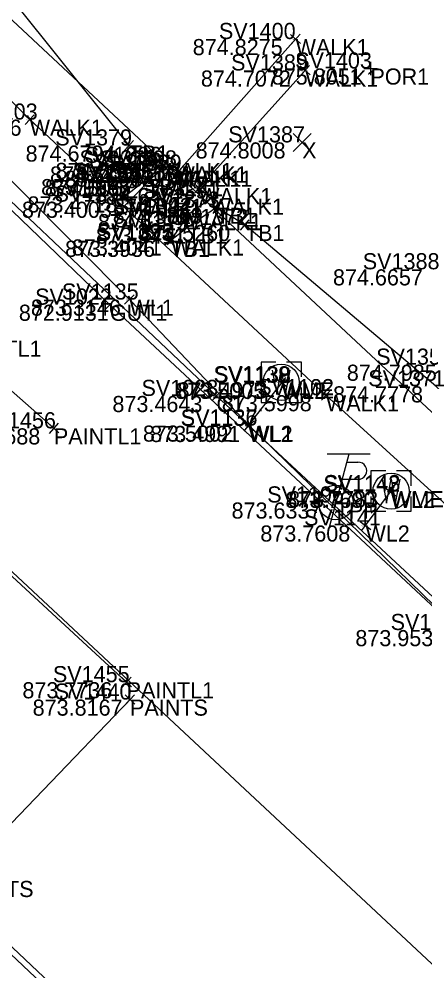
# Model space of a CAD drawing. Extents: x 1469677 to 1493262, y 375219 to 389293.
# Drawn here: x 1480132 to 1480162.2, y 379434.1 to 379505 of the extents above; entities that cross this region are included whole.
import ezdxf

# ---------------------------------------------------------------- set-up
doc = ezdxf.new("R2010")
doc.units = 0
for name, color, linetype in [('Building', 7, 'Continuous'), ('DR_X_Drive_Pipe', 7, 'Continuous'), ('DV_X_Lot_Line', 7, 'Continuous'), ('DV_X_Text', 7, 'Continuous'), ('GK_Visualization', 7, 'Continuous'), ('PNTELEV', 7, 'Continuous'), ('PNTNO', 7, 'Continuous'), ('PNTS', 7, 'Continuous'), ('PV_X_Curb', 7, 'Continuous'), ('RD_P_Text', 7, 'Continuous'), ('RW_P_Esmt_SW', 7, 'Continuous'), ('RW_P_Esmt_U', 7, 'Continuous'), ('SV_X_Mon_Cells_Found', 7, 'Continuous'), ('SV_X_Text', 7, 'Continuous'), ('SV_X_Text_Elevation', 7, 'Continuous')]:
    doc.layers.add(name, color=color, linetype=linetype)

msp = doc.modelspace()

# ---------------------------------------------------------------- linework, layer by layer
at = {"layer": 'Building'}
for points in [[(1480030.312, 379558.368), (1480048.994, 379540.544), (1480068.184, 379522.458), (1480086.697, 379505.162), (1480104.247, 379488.61), (1480122.276, 379471.896), (1480139.96, 379455.601)], [(1480134.548, 379474.499), (1480127.117, 379481.028)]]:
    msp.add_lwpolyline(points, dxfattribs=at)
at = {"layer": 'DR_X_Drive_Pipe'}
for points in [[(1480049.152, 379568.017), (1480068.611, 379550.193), (1480086.403, 379533.424), (1480090.024, 379530.079), (1480102.295, 379519.134), (1480111.734, 379511.473), (1480120.332, 379509.136), (1480127.535, 379501.668), (1480127.911, 379496.395), (1480140.166, 379484.084), (1480149.088, 379474.708), (1480164.726, 379459.482), (1480172.622, 379452.503), (1480197.813, 379429.111)], [(1480149.013, 379474.68), (1480151.509, 379477.889)], [(1480157.731, 379467.268), (1480159.603, 379469.773)]]:
    msp.add_lwpolyline(points, dxfattribs=at)
at = {"layer": 'DV_X_Lot_Line'}
for points in [[(1480215.341, 379421.047), (1480197.466, 379437.463), (1480177.803, 379455.97), (1480154.79, 379476.967), (1480132.747, 379497.48), (1480113.376, 379516.728), (1480110.754, 379519.04), (1480109.877, 379518.336), (1480091.944, 379535.267), (1480093.027, 379536.619), (1480090.219, 379539.243), (1480090.463, 379539.725), (1480084.681, 379544.882), (1480083.843, 379544.144), (1480066.818, 379560.524), (1480045.662, 379580.046)], [(1480140.103, 379491.371), (1480141.696, 379492.981), (1480142.433, 379494.261), (1480143.057, 379493.677), (1480143.514, 379493.991), (1480143.87, 379493.684), (1480152.532, 379503.479)], [(1480153.241, 379501.138), (1480145.352, 379492.379), (1480146.223, 379491.6), (1480144.597, 379490.448), (1480143.265, 379488.564)]]:
    msp.add_lwpolyline(points, dxfattribs=at)
at = {"layer": 'PNTELEV'}
for p, q in [((1480152.158, 379503.81), (1480152.907, 379503.148)), ((1480152.201, 379503.104), (1480152.864, 379503.853)), ((1480152.532, 379503.479), (1480152.532, 379503.479)), ((1480158.103, 379501.787), (1480158.103, 379500.787)), ((1480153.613, 379500.803), (1480152.87, 379501.473)), ((1480153.576, 379501.509), (1480152.907, 379500.766)), ((1480153.241, 379501.138), (1480153.241, 379501.138)), ((1480157.603, 379501.287), (1480158.603, 379501.287)), ((1480158.103, 379501.287), (1480158.103, 379501.287)), ((1480133.113, 379497.14), (1480132.381, 379497.821)), ((1480132.406, 379497.114), (1480133.087, 379497.846)), ((1480132.747, 379497.48), (1480132.747, 379497.48)), ((1480140.516, 379495.228), (1480139.76, 379495.882)), ((1480139.811, 379495.177), (1480140.465, 379495.933)), ((1480140.138, 379495.555), (1480140.138, 379495.555)), ((1480142.183, 379493.828), (1480142.682, 379494.695)), ((1480141.498, 379494.236), (1480142.377, 379493.76)), ((1480141.699, 379493.559), (1480142.175, 379494.438)), ((1480141.937, 379493.998), (1480141.937, 379493.998)), ((1480141.999, 379494.511), (1480142.866, 379494.012)), ((1480142.433, 379494.261), (1480142.433, 379494.261)), ((1480142.692, 379494.019), (1480143.422, 379493.335)), ((1480143.399, 379494.042), (1480142.715, 379493.312)), ((1480143.102, 379493.708), (1480143.927, 379494.273)), ((1480143.231, 379494.403), (1480143.797, 379493.578)), ((1480143.491, 379494.011), (1480144.248, 379493.358)), ((1480143.514, 379493.991), (1480143.514, 379493.991)), ((1480144.196, 379494.063), (1480143.543, 379493.306)), ((1480141.036, 379492.744), (1480141.818, 379493.368)), ((1480141.115, 379493.447), (1480141.739, 379492.665)), ((1480141.34, 379493.332), (1480142.051, 379492.629)), ((1480141.344, 379492.625), (1480142.047, 379493.336)), ((1480143.057, 379493.677), (1480143.057, 379493.677)), ((1480143.87, 379493.684), (1480143.87, 379493.684)), ((1480141.427, 379493.056), (1480141.427, 379493.056)), ((1480141.696, 379492.981), (1480141.696, 379492.981)), ((1480145.724, 379492.045), (1480144.981, 379492.714)), ((1480145.687, 379492.751), (1480145.018, 379492.008)), ((1480139.417, 379491.453), (1480140.199, 379492.076)), ((1480139.496, 379492.156), (1480140.12, 379491.374)), ((1480139.808, 379491.765), (1480139.808, 379491.765)), ((1480145.352, 379492.379), (1480145.352, 379492.379)), ((1480145.851, 379491.933), (1480146.595, 379491.266)), ((1480146.557, 379491.972), (1480145.889, 379491.227)), ((1480139.748, 379491.723), (1480140.459, 379491.02)), ((1480139.752, 379491.016), (1480140.455, 379491.727)), ((1480140.103, 379491.371), (1480140.103, 379491.371)), ((1480147.076, 379490.666), (1480146.222, 379491.186)), ((1480146.223, 379491.6), (1480146.223, 379491.6)), ((1480146.389, 379490.499), (1480146.91, 379491.353)), ((1480145.005, 379490.737), (1480144.189, 379490.159)), ((1480144.886, 379490.04), (1480144.308, 379490.856)), ((1480144.597, 379490.448), (1480144.597, 379490.448)), ((1480146.649, 379490.926), (1480146.649, 379490.926)), ((1480144.896, 379489.728), (1480144.07, 379489.164)), ((1480144.765, 379489.033), (1480144.201, 379489.859)), ((1480149.146, 379489.315), (1480148.382, 379489.96)), ((1480148.441, 379489.256), (1480149.087, 379490.019)), ((1480148.764, 379489.638), (1480148.764, 379489.638)), ((1480143.554, 379488.973), (1480142.976, 379488.156)), ((1480144.483, 379489.446), (1480144.483, 379489.446)), ((1480143.607, 379488.769), (1480142.816, 379488.157)), ((1480143.673, 379488.276), (1480142.857, 379488.853)), ((1480143.518, 379488.068), (1480142.906, 379488.859)), ((1480143.212, 379488.463), (1480143.212, 379488.463)), ((1480143.265, 379488.564), (1480143.265, 379488.564)), ((1480138.353, 379484.05), (1480139.074, 379483.357)), ((1480139.06, 379484.064), (1480138.367, 379483.343)), ((1480140.52, 379484.437), (1480139.812, 379483.732)), ((1480139.813, 379484.439), (1480140.519, 379483.73)), ((1480140.166, 379484.084), (1480140.166, 379484.084)), ((1480138.714, 379483.703), (1480138.714, 379483.703)), ((1480151.114, 379478.196), (1480151.904, 379477.582)), ((1480151.202, 379477.495), (1480151.816, 379478.284)), ((1480151.509, 379477.889), (1480151.509, 379477.889)), ((1480146.277, 379477.253), (1480147.003, 379476.565)), ((1480146.983, 379477.272), (1480146.296, 379476.546)), ((1480146.64, 379476.909), (1480146.64, 379476.909)), ((1480155.159, 379476.63), (1480154.42, 379477.304)), ((1480154.453, 379476.598), (1480155.127, 379477.337)), ((1480154.79, 379476.967), (1480154.79, 379476.967)), ((1480134.924, 379474.169), (1480134.172, 379474.829)), ((1480134.218, 379474.124), (1480134.878, 379474.875)), ((1480148.618, 379474.987), (1480149.407, 379474.373)), ((1480148.706, 379474.285), (1480149.32, 379475.074)), ((1480149.45, 379475.053), (1480148.725, 379474.363)), ((1480148.743, 379475.07), (1480149.432, 379474.346)), ((1480134.548, 379474.499), (1480134.548, 379474.499)), ((1480149.013, 379474.68), (1480149.013, 379474.68)), ((1480149.088, 379474.708), (1480149.088, 379474.708)), ((1480159.203, 379470.072), (1480160.004, 379469.473)), ((1480159.304, 379469.372), (1480159.903, 379470.173)), ((1480159.603, 379469.773), (1480159.603, 379469.773)), ((1480157.432, 379466.868), (1480158.031, 379467.669)), ((1480157.331, 379467.567), (1480158.132, 379466.969)), ((1480157.731, 379467.268), (1480157.731, 379467.268)), ((1480139.593, 379455.939), (1480140.328, 379455.262)), ((1480140.299, 379455.968), (1480139.621, 379455.233)), ((1480139.96, 379455.601), (1480139.96, 379455.601)), ((1480139.849, 379454.655), (1480140.57, 379453.962)), ((1480139.863, 379453.948), (1480140.556, 379454.669)), ((1480140.21, 379454.309), (1480140.21, 379454.309))]:
    msp.add_line(p, q, dxfattribs=at)
at = {"layer": 'PNTNO'}
for p, q in [((1480151.46, 379477.928), (1480151.46, 379477.928)), ((1480159.64, 379469.823), (1480159.64, 379469.823))]:
    msp.add_line(p, q, dxfattribs=at)
for points in [[(1480151.06, 379479.428), (1480149.96, 379479.428), (1480149.96, 379478.328)], [(1480152.96, 379478.328), (1480152.96, 379479.428), (1480151.86, 379479.428)], [(1480150.793, 379478.828), (1480151.126, 379477.028), (1480151.46, 379478.828), (1480151.793, 379477.028), (1480152.126, 379478.828)], [(1480149.96, 379477.528), (1480149.96, 379476.428), (1480151.06, 379476.428)], [(1480151.86, 379476.428), (1480152.96, 379476.428), (1480152.96, 379477.528)], [(1480159.24, 379471.323), (1480158.14, 379471.323), (1480158.14, 379470.223)], [(1480161.14, 379470.223), (1480161.14, 379471.323), (1480160.04, 379471.323)], [(1480158.973, 379470.723), (1480159.306, 379468.923), (1480159.64, 379470.723), (1480159.973, 379468.923), (1480160.306, 379470.723)], [(1480158.14, 379469.423), (1480158.14, 379468.323), (1480159.24, 379468.323)], [(1480160.04, 379468.323), (1480161.14, 379468.323), (1480161.14, 379469.423)]]:
    msp.add_lwpolyline(points, dxfattribs=at)
for centre in [(1480151.46, 379477.928), (1480159.64, 379469.823)]:
    msp.add_circle(centre, 1.35, dxfattribs=at)
at = {"layer": 'PNTS'}
for p, q in [((1480156.487, 379472.579), (1480154.88, 379466.579)), ((1480158.087, 379472.579), (1480154.887, 379472.579)), ((1480156.327, 379471.979), (1480157.177, 379471.979)), ((1480155.985, 379470.704), (1480157.177, 379470.704))]:
    msp.add_line(p, q, dxfattribs=at)
msp.add_circle((1480155.523, 379468.979), 1.3, dxfattribs=at)
msp.add_arc((1480157.189, 379471.341), 0.638, 268.8767, 91.1233, dxfattribs=at)
at = {"layer": 'PV_X_Curb'}
for points in [[(1480139.808, 379491.765), (1480141.427, 379493.056), (1480141.937, 379493.998), (1480140.138, 379495.555), (1480131.076, 379506.913), (1480127.878, 379509.549), (1480127.257, 379513.845), (1480127.148, 379513.859), (1480132.645, 379520.158)], [(1480170.345, 379463.114), (1480171.936, 379465.283), (1480168.947, 379471.416), (1480162.966, 379477.627), (1480148.764, 379489.638), (1480146.649, 379490.926), (1480144.483, 379489.446), (1480143.212, 379488.463)]]:
    msp.add_lwpolyline(points, dxfattribs=at)
at = {"layer": 'RD_P_Text'}
for points in [[(1480043.308, 379574.086), (1480051.435, 379566.534), (1480067.64, 379551.083), (1480087.827, 379532.141), (1480105.189, 379515.816), (1480105.937, 379515.205), (1480115.287, 379506.588), (1480116.588, 379505.377), (1480116.999, 379505.563), (1480121.373, 379501.34), (1480121.053, 379501.135), (1480146.64, 379476.909), (1480171.177, 379454.102), (1480173.021, 379452.229), (1480182.175, 379443.675), (1480183.379, 379442.683), (1480186.184, 379440.013), (1480186.975, 379439.363), (1480207.407, 379420.301)], [(1480042.95, 379573.802), (1480051.182, 379566.018), (1480067.383, 379550.834), (1480087.586, 379531.809), (1480105.067, 379515.41), (1480105.589, 379514.887), (1480115.079, 379506.297), (1480116.303, 379505.052), (1480118.53, 379502.967), (1480120.902, 379500.821), (1480138.714, 379483.703), (1480170.84, 379453.681), (1480172.574, 379452.083), (1480181.867, 379443.345), (1480182.839, 379442.217), (1480185.607, 379439.661), (1480186.493, 379438.955), (1480206.919, 379419.855)], [(1480135.19, 379432.332), (1480118.45, 379448.16), (1480110.152, 379455.954), (1480109.273, 379456.61), (1480100.92, 379464.722), (1480096.044, 379469.27), (1480093.779, 379471.437), (1480091.422, 379473.761), (1480089.145, 379475.876), (1480069.411, 379494.504), (1480056.455, 379506.379), (1480055.435, 379507.417), (1480042.302, 379520.019), (1480041.64, 379520.833), (1480030.984, 379530.729), (1480016.059, 379544.67)], [(1480135, 379431.897), (1480118.039, 379447.914), (1480109.91, 379455.647), (1480108.98, 379456.443), (1480100.472, 379464.439), (1480095.645, 379469.163), (1480093.387, 379471.311), (1480093.127, 379470.939), (1480088.623, 379475.041), (1480088.838, 379475.368), (1480068.906, 379494.276), (1480056.264, 379506.212), (1480055.202, 379507.245), (1480042.335, 379519.353), (1480041.39, 379520.138), (1480030.539, 379530.321), (1480016.21, 379543.914)]]:
    msp.add_lwpolyline(points, dxfattribs=at)
at = {"layer": 'RW_P_Esmt_U'}
for p, q in [((1480152.352, 379495.119), (1480153.685, 379496.454)), ((1480152.352, 379496.454), (1480153.685, 379495.119))]:
    msp.add_line(p, q, dxfattribs=at)
at = {"layer": 'SV_X_Mon_Cells_Found'}
msp.add_lwpolyline([(1477206.544, 382340.781), (1479657.335, 379947.979), (1480466.338, 379191.878)], dxfattribs=at)
at = {"layer": 'SV_X_Text'}
msp.add_lwpolyline([(1480127.237, 379440.807), (1480140.21, 379454.309)], dxfattribs=at)
at = {"layer": 'SV_X_Text_Elevation'}
msp.add_line((1479636.611, 379926.284), (1480557.828, 379065.308), dxfattribs=at)

# ---------------------------------------------------------------- texts
at = {"layer": 'DV_X_Text'}
for s, height, p in [('874.8275', 1.2, (1480144.879, 379502.279)), ('874.83', 0.06, (1480152.251, 379503.419)), ('874.7072', 1.2, (1480145.484, 379499.938)), ('875.8051', 1.2, (1480150.759, 379500.087)), ('874.71', 0.06, (1480152.984, 379501.078)), ('875.81', 0.06, (1480157.845, 379501.227)), ('873.1376', 1.2, (1480125.444, 379496.28)), ('873.14', 0.06, (1480132.49, 379497.42)), ('874.6794', 1.2, (1480132.438, 379494.355)), ('874.68', 0.06, (1480139.856, 379495.495)), ('874.8008', 1.2, (1480145.092, 379494.586)), ('874.80', 0.06, (1480152.733, 379495.726)), ('874.5794', 1.2, (1480134.256, 379492.798)), ('874.5856', 1.2, (1480134.666, 379493.061)), ('874.6910', 1.2, (1480136.155, 379492.791)), ('874.58', 0.06, (1480141.656, 379493.938)), ('874.59', 0.06, (1480142.152, 379494.201)), ('874.69', 0.06, (1480143.232, 379493.931)), ('874.6483', 1.2, (1480135.338, 379492.477)), ('874.6422', 1.2, (1480136.179, 379492.484)), ('874.65', 0.06, (1480142.775, 379493.617)), ('874.64', 0.06, (1480143.589, 379493.624)), ('873.9966', 1.2, (1480133.595, 379491.856)), ('874.5067', 1.2, (1480133.873, 379491.781)), ('874.00', 0.06, (1480141.136, 379492.996)), ('874.51', 0.06, (1480141.438, 379492.921)), ('873.4718', 1.2, (1480132.581, 379490.565)), ('874.6452', 1.2, (1480137.643, 379491.179)), ('873.47', 0.06, (1480139.526, 379491.705)), ('874.65', 0.06, (1480145.07, 379492.319)), ('873.4003', 1.2, (1480132.167, 379490.171)), ('874.6441', 1.2, (1480138.946, 379490.4)), ('873.40', 0.06, (1480139.816, 379491.311)), ('874.64', 0.06, (1480145.942, 379491.54)), ('874.6119', 1.2, (1480137.824, 379489.248)), ('874.5869', 1.2, (1480138.93, 379489.726)), ('874.61', 0.06, (1480144.338, 379490.388)), ('874.59', 0.06, (1480146.368, 379490.866)), ('874.5260', 1.2, (1480140.969, 379488.438)), ('874.53', 0.06, (1480148.483, 379489.578)), ('873.9411', 1.2, (1480137.679, 379488.246)), ('873.94', 0.06, (1480144.201, 379489.386)), ('873.3936', 1.2, (1480135.379, 379487.263)), ('873.4041', 1.2, (1480135.884, 379487.364)), ('873.39', 0.06, (1480142.929, 379488.403)), ('873.40', 0.06, (1480142.978, 379488.504)), ('874.6657', 1.2, (1480155.312, 379485.138)), ('873.3146', 1.2, (1480132.835, 379482.884)), ('873.31', 0.06, (1480139.907, 379484.024)), ('872.9131', 1.2, (1480131.938, 379482.503)), ('872.91', 0.06, (1480138.456, 379483.643)), ('874.7985', 1.2, (1480156.346, 379478.037)), ('873.5005', 1.2, (1480143.582, 379476.689)), ('873.4973', 1.2, (1480143.75, 379476.728)), ('873.50', 0.06, (1480151.174, 379477.868)), ('873.50', 0.06, (1480151.223, 379477.829)), ('874.7778', 1.2, (1480155.322, 379476.427)), ('873.4643', 1.2, (1480138.902, 379475.709)), ('873.46', 0.06, (1480146.355, 379476.849)), ('873.5998', 1.2, (1480147.042, 379475.767)), ('873.60', 0.06, (1480154.503, 379476.907)), ('873.2688', 1.2, (1480126.838, 379473.299)), ('873.27', 0.06, (1480134.268, 379474.439)), ('873.5002', 1.2, (1480141.17, 379473.508)), ('873.4991', 1.2, (1480141.716, 379473.48)), ('873.50', 0.06, (1480148.727, 379474.62)), ('873.50', 0.06, (1480148.802, 379474.648)), ('873.7783', 1.2, (1480151.977, 379468.623)), ('873.78', 0.06, (1480159.359, 379469.763)), ('873.7690', 1.2, (1480151.78, 379468.573)), ('873.77', 0.06, (1480159.323, 379469.713)), ('873.6337', 1.2, (1480147.766, 379467.779)), ('873.63', 0.06, (1480155.241, 379468.919)), ('873.7608', 1.2, (1480149.908, 379466.068)), ('873.76', 0.06, (1480157.447, 379467.208)), ('873.9538', 1.2, (1480156.978, 379458.282)), ('873.7736', 1.2, (1480132.203, 379454.401)), ('873.77', 0.06, (1480139.68, 379455.541)), ('873.8167', 1.2, (1480132.964, 379453.109)), ('873.82', 0.06, (1480139.929, 379454.249))]:
    msp.add_text(s, height=height, dxfattribs=at).set_placement(p)
at = {"layer": 'GK_Visualization'}
for s, p in [('WALK1', (1480152.532, 379502.279)), ('WALK1', (1480153.241, 379499.938)), ('POR1', (1480158.103, 379500.087)), ('WALK1', (1480132.747, 379496.28)), ('TB1', (1480140.138, 379494.355)), ('X', (1480153.019, 379494.586)), ('TB1', (1480141.937, 379492.798)), ('WALK1', (1480142.433, 379493.061)), ('WALK1', (1480143.514, 379492.791)), ('WALK1', (1480143.057, 379492.477)), ('WALK1', (1480143.87, 379492.484)), ('TB1', (1480141.427, 379491.856)), ('WALK1', (1480141.696, 379491.781)), ('TB1', (1480139.808, 379490.565)), ('WALK1', (1480145.352, 379491.179)), ('WALK1', (1480140.103, 379490.171)), ('WALK1', (1480146.223, 379490.4)), ('WALK1', (1480144.597, 379489.248)), ('TB1', (1480146.649, 379489.726)), ('TB1', (1480148.764, 379488.438)), ('TB1', (1480144.483, 379488.246)), ('TB1', (1480143.212, 379487.263)), ('WALK1', (1480143.265, 379487.364)), ('WL1', (1480140.166, 379482.884)), ('GUT1', (1480138.714, 379482.503)), ('PAINTL1', (1480127.117, 379479.828)), ('WME', (1480151.46, 379476.728)), ('WL2', (1480151.509, 379476.689)), ('C1', (1480146.64, 379475.709)), ('WALK1', (1480154.79, 379475.767)), ('PAINTL1', (1480134.548, 379473.299)), ('WL2', (1480149.013, 379473.48)), ('WL1', (1480149.088, 379473.508)), ('WME', (1480159.64, 379468.623)), ('WL2', (1480159.603, 379468.573)), ('TPP', (1480155.523, 379467.779)), ('WL2', (1480157.731, 379466.068)), ('PAINTL1', (1480139.96, 379454.401)), ('PAINTS', (1480140.21, 379453.109)), ('PAINTS', (1480127.237, 379439.607))]:
    msp.add_text(s, height=1.2, dxfattribs=at).set_placement(p)
at = {"layer": 'RW_P_Esmt_SW'}
for s, height, p in [('SV1400', 1.2, (1480146.826, 379503.479)), ('SV1400', 0.06, (1480152.247, 379503.479)), ('SV1403', 1.2, (1480152.501, 379501.287)), ('SV1389', 1.2, (1480147.734, 379501.138)), ('SV1389', 0.06, (1480152.966, 379501.138)), ('SV1403', 0.06, (1480157.823, 379501.287)), ('SV1103', 1.2, (1480127.627, 379497.48)), ('SV1103', 0.06, (1480132.491, 379497.48)), ('SV1379', 1.2, (1480134.649, 379495.555)), ('SV1387', 1.2, (1480147.521, 379495.786)), ('SV1396', 1.2, (1480136.84, 379494.261)), ('SV1379', 0.06, (1480139.864, 379495.555)), ('SV1387', 0.06, (1480152.744, 379495.786)), ('SV1378', 1.2, (1480136.449, 379493.998)), ('SV1397', 1.2, (1480137.54, 379493.677)), ('SV1398', 1.2, (1480137.988, 379493.991)), ('SV1399', 1.2, (1480138.343, 379493.684)), ('SV1377', 1.2, (1480135.948, 379493.056)), ('SV1395', 1.2, (1480136.179, 379492.981)), ('SV1378', 0.06, (1480141.663, 379493.998)), ('SV1396', 0.06, (1480142.153, 379494.261)), ('SV1398', 0.06, (1480143.238, 379493.991)), ('SV1390', 1.2, (1480139.731, 379492.379)), ('SV1397', 0.06, (1480142.781, 379493.677)), ('SV1399', 0.06, (1480143.594, 379493.684)), ('SV1376', 1.2, (1480134.253, 379491.765)), ('SV1394', 1.2, (1480134.596, 379491.371)), ('SV1377', 0.06, (1480141.153, 379493.056)), ('SV1391', 1.2, (1480141.157, 379491.6)), ('SV1395', 0.06, (1480141.42, 379492.981)), ('SV1376', 0.06, (1480139.53, 379491.765)), ('SV1373', 1.2, (1480141.17, 379490.926)), ('SV1390', 0.06, (1480145.071, 379492.379)), ('SV1392', 1.2, (1480139.089, 379490.448)), ('SV1394', 0.06, (1480139.828, 379491.371)), ('SV1391', 0.06, (1480145.97, 379491.6)), ('SV1374', 1.2, (1480139.013, 379489.446)), ('SV1372', 1.2, (1480143.294, 379489.638)), ('SV1392', 0.06, (1480144.322, 379490.448)), ('SV1373', 0.06, (1480146.375, 379490.926)), ('SV1375', 1.2, (1480137.732, 379488.463)), ('SV1393', 1.2, (1480137.748, 379488.564)), ('SV1372', 0.06, (1480148.491, 379489.638)), ('SV1374', 0.06, (1480144.21, 379489.446)), ('SV1375', 0.06, (1480142.938, 379488.463)), ('SV1393', 0.06, (1480142.989, 379488.564)), ('SV1388', 1.2, (1480157.533, 379486.338)), ('SV1022', 1.2, (1480133.149, 379483.703)), ('SV1135', 1.2, (1480135.141, 379484.084)), ('SV1135', 0.06, (1480139.915, 379484.084)), ('SV1022', 0.06, (1480138.436, 379483.703)), ('SV1358', 1.2, (1480158.529, 379479.237)), ('SV1139', 1.2, (1480146.425, 379477.928)), ('SV1138', 1.2, (1480146.474, 379477.889)), ('SV1371', 1.2, (1480157.938, 379477.627)), ('SV1023', 1.2, (1480141.066, 379476.909)), ('SV1102', 1.2, (1480149.679, 379476.967)), ('SV1139', 0.06, (1480151.208, 379477.928)), ('SV1138', 0.06, (1480151.257, 379477.889)), ('SV1023', 0.06, (1480146.361, 379476.909)), ('SV1102', 0.06, (1480154.534, 379476.967)), ('SV1456', 1.2, (1480128.984, 379474.499)), ('SV1136', 1.2, (1480143.987, 379474.708)), ('SV1137', 1.2, (1480143.987, 379474.68)), ('SV1136', 0.06, (1480148.833, 379474.708)), ('SV1456', 0.06, (1480134.27, 379474.499)), ('SV1137', 0.06, (1480148.762, 379474.68)), ('SV1142', 1.2, (1480154.597, 379469.773)), ('SV1143', 1.2, (1480154.624, 379469.823)), ('SV1196', 1.2, (1480150.423, 379468.979)), ('SV1142', 0.06, (1480159.353, 379469.773)), ('SV1143', 0.06, (1480159.389, 379469.823)), ('SV1141', 1.2, (1480153.167, 379467.268)), ('SV1196', 0.06, (1480155.268, 379468.979)), ('SV1141', 0.06, (1480157.503, 379467.268)), ('SV1140', 1.2, (1480159.606, 379459.482)), ('SV1455', 1.2, (1480134.472, 379455.601)), ('SV1455', 0.06, (1480139.686, 379455.601)), ('SV1440', 1.2, (1480134.608, 379454.309)), ('SV1440', 0.06, (1480139.93, 379454.309))]:
    msp.add_text(s, height=height, dxfattribs=at).set_placement(p)

doc.saveas('drawing.dxf')
